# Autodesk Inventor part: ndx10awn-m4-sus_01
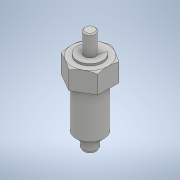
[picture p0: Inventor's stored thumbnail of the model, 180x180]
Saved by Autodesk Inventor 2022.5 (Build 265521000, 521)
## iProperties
Part Number: ndx10awn-m4-sus_01
Material: 一般
Document SubType Name: Modeling
Designer: ImaoCorp
Density: 1 g/cm^3
Appearance: 既定
Author: ImaoCorp
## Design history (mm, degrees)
feature "ndx10awn-m4-sus_01"
node "ソリッド1"
